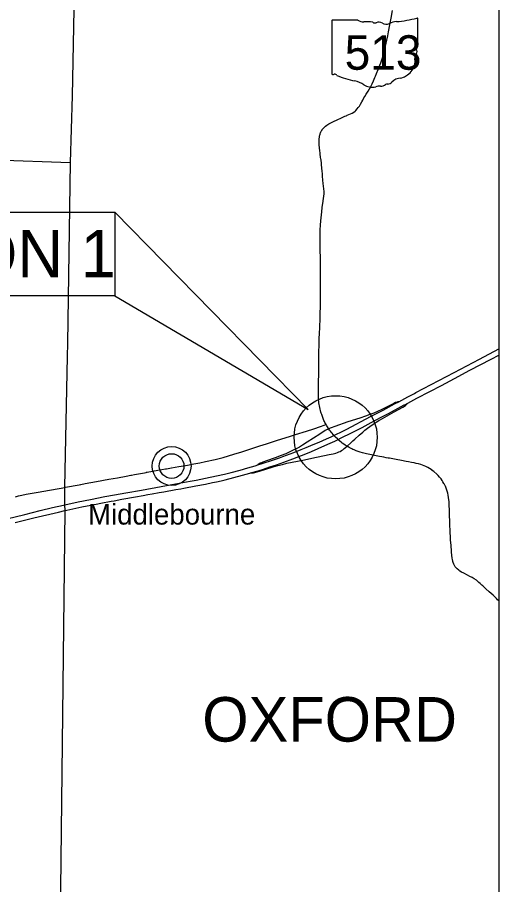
# Model space of a CAD drawing. Extents: x -29.6 to 34, y 0 to 22.
# Drawn here: x -12.475 to -10.748, y 3.392 to 6.503 of the extents above; entities that cross this region are included whole.
import ezdxf

# ---------------------------------------------------------------- set-up
doc = ezdxf.new("R2010")
doc.units = 0
for name, color, linetype in [('BR_P_Gen_Text', 7, 'Continuous'), ('Default', 7, 'Continuous'), ('GM_X_County_Road', 7, 'Continuous'), ('GM_X_Interchange_Ramps', 7, 'Continuous'), ('GM_X_Interstate_Route', 7, 'Continuous'), ('GM_X_State_Route', 7, 'Continuous'), ('GM_X_State_Shield', 7, 'Continuous'), ('GM_X_Township', 7, 'Continuous'), ('GM_X_Township_Text', 7, 'Continuous'), ('GM_X_Unincorporated', 7, 'Continuous'), ('GM_X_Unincorporated_Location', 7, 'Continuous'), ('GM_X_Unincorporated_Text', 7, 'Continuous'), ('GM_X_US_Route', 7, 'Continuous'), ('SH_Text', 7, 'Continuous')]:
    doc.layers.add(name, color=color, linetype=linetype)

msp = doc.modelspace()

# ---------------------------------------------------------------- linework, layer by layer
at = {"layer": 'BR_P_Gen_Text'}
for points in [[(-13.5333, 5.8042), (-12.1246, 5.8042), (-12.1246, 5.504), (-13.5333, 5.504)], [(-12.1246, 5.8042), (-12.1246, 5.504), (-11.4311, 5.0966)]]:
    msp.add_lwpolyline(points, close=True, dxfattribs=at)
at = {"layer": 'Default'}
msp.add_circle((-11.3326, 4.9969), 0.149, dxfattribs=at)
at = {"layer": 'GM_X_County_Road'}
for points in [[(-11.8865, 4.8935), (-11.8639, 4.8975), (-11.8418, 4.9017), (-11.8201, 4.9059), (-11.7991, 4.91), (-11.7653, 4.9176), (-11.7359, 4.9251), (-11.7174, 4.9303), (-11.6985, 4.9359), (-11.6694, 4.945), (-11.6403, 4.9544), (-11.6048, 4.9658), (-11.5812, 4.9733), (-11.5444, 4.9851), (-11.495, 5.0005), (-11.4767, 5.0065), (-11.4371, 5.0195), (-11.4109, 5.0277), (-11.3866, 5.0362), (-11.3733, 5.0405), (-11.3672, 5.0424)], [(-11.94, 4.8838), (-11.9337, 4.885), (-11.9216, 4.8872), (-11.8952, 4.892), (-11.8865, 4.8935)], [(-12.2531, 4.8269), (-12.2486, 4.8276), (-12.2473, 4.8279), (-12.2307, 4.8312), (-12.1911, 4.8381), (-12.1459, 4.8465), (-12.1149, 4.852), (-12.084, 4.8578), (-12.0674, 4.8608), (-12.0653, 4.8612)], [(-12.0653, 4.8612), (-12.0548, 4.863), (-12.0181, 4.87), (-12.0124, 4.8712), (-12.0115, 4.8714)], [(-12.0115, 4.8714), (-12.009, 4.8718), (-11.9895, 4.8753), (-11.971, 4.8785), (-11.9566, 4.8809), (-11.9425, 4.8833), (-11.94, 4.8838)], [(-12.3047, 4.8174), (-12.302, 4.8179), (-12.2531, 4.8269)], [(-12.4817, 4.7837), (-12.471, 4.7865), (-12.459, 4.7894), (-12.443, 4.7926), (-12.3995, 4.8006), (-12.38, 4.8041), (-12.3047, 4.8174)]]:
    msp.add_lwpolyline(points, dxfattribs=at)
at = {"layer": 'GM_X_Interchange_Ramps'}
for points in [[(-11.1062, 5.1247), (-11.1095, 5.1242), (-11.1123, 5.1234), (-11.1178, 5.1214), (-11.1236, 5.1186), (-11.1402, 5.1103), (-11.1668, 5.097), (-11.1826, 5.0895), (-11.1954, 5.0839), (-11.2101, 5.0782), (-11.226, 5.0725), (-11.2454, 5.066), (-11.2886, 5.0519), (-11.335, 5.0361), (-11.3493, 5.0311), (-11.358, 5.0278)], [(-11.2917, 4.965), (-11.2899, 4.9666), (-11.2795, 4.9759), (-11.2709, 4.9837), (-11.2636, 4.9904), (-11.2477, 5.0049), (-11.2355, 5.0158), (-11.2279, 5.0222), (-11.2188, 5.0294), (-11.2104, 5.0357), (-11.198, 5.0443), (-11.1877, 5.051), (-11.1773, 5.0574), (-11.1642, 5.0649), (-11.1229, 5.0878), (-11.0922, 5.1046), (-11.0856, 5.1088), (-11.0819, 5.1116), (-11.0776, 5.1156), (-11.0737, 5.1196)], [(-11.358, 5.0278), (-11.3624, 5.0255), (-11.366, 5.0235), (-11.3699, 5.0211), (-11.3899, 5.008), (-11.4344, 4.9792), (-11.4511, 4.9687), (-11.4621, 4.9621), (-11.4739, 4.9556), (-11.4869, 4.9491), (-11.4996, 4.9432), (-11.5119, 4.9379), (-11.5282, 4.9315), (-11.5495, 4.9237), (-11.5806, 4.9127), (-11.5935, 4.9077), (-11.599, 4.9055), (-11.6029, 4.9037), (-11.6074, 4.9012), (-11.6118, 4.898)], [(-11.6377, 4.8692), (-11.6331, 4.8693), (-11.6274, 4.8701), (-11.622, 4.8711), (-11.6064, 4.8757), (-11.5569, 4.8911), (-11.5401, 4.8959), (-11.5237, 4.9), (-11.5073, 4.9037), (-11.469, 4.9116), (-11.4445, 4.9166), (-11.4177, 4.9221), (-11.3557, 4.935), (-11.3415, 4.9381), (-11.3324, 4.9404), (-11.3258, 4.9425), (-11.3209, 4.9445), (-11.3168, 4.9465), (-11.3117, 4.9494), (-11.3069, 4.9526), (-11.3018, 4.9565), (-11.2917, 4.965)]]:
    msp.add_lwpolyline(points, dxfattribs=at)
at = {"layer": 'GM_X_Interstate_Route'}
for points in [[(-11.0737, 5.1196), (-11.041, 5.1369), (-10.9946, 5.1613), (-10.9529, 5.1833), (-10.9066, 5.2077), (-10.851, 5.2372), (-10.7749, 5.2775), (-10.7478, 5.2918)], [(-11.0498, 5.1544), (-11.0448, 5.1571), (-10.9902, 5.1858), (-10.9075, 5.2298), (-10.8168, 5.2775), (-10.7478, 5.3139)], [(-11.6118, 4.898), (-11.5923, 4.904), (-11.5629, 4.9136), (-11.5342, 4.9234), (-11.5216, 4.9279), (-11.509, 4.9326), (-11.4823, 4.9427), (-11.4563, 4.953), (-11.4385, 4.9602), (-11.4132, 4.9708), (-11.3918, 4.98), (-11.3658, 4.9917), (-11.3493, 4.9992), (-11.3391, 5.0039), (-11.3319, 5.0072), (-11.3119, 5.0168), (-11.2927, 5.0265), (-11.2075, 5.0712), (-11.1627, 5.0948), (-11.121, 5.1168), (-11.1062, 5.1247), (-11.0732, 5.1422), (-11.0498, 5.1544)], [(-11.3266, 4.9878), (-11.3241, 4.989), (-11.3123, 4.9947), (-11.2753, 5.0132), (-11.2379, 5.0322), (-11.2049, 5.0496), (-11.1665, 5.0703), (-11.1434, 5.0827), (-11.0864, 5.1129)], [(-11.0864, 5.1129), (-11.0847, 5.1138), (-11.0737, 5.1196)], [(-11.6377, 4.8692), (-11.611, 4.8771), (-11.5916, 4.8832), (-11.5683, 4.8908), (-11.5451, 4.8986), (-11.5188, 4.9079), (-11.4865, 4.9196), (-11.4653, 4.9277), (-11.4452, 4.9356), (-11.4189, 4.9465), (-11.3948, 4.9569), (-11.3602, 4.9722), (-11.3359, 4.9834), (-11.3266, 4.9878)], [(-12.5124, 4.705), (-12.4478, 4.7204), (-12.3924, 4.7341), (-12.3482, 4.7446), (-12.3096, 4.7535), (-12.3047, 4.7545), (-12.2561, 4.7651), (-12.2127, 4.774), (-12.1607, 4.7841), (-12.1258, 4.7905), (-12.0856, 4.7977), (-12.0288, 4.8078), (-11.9073, 4.8295), (-11.8545, 4.8391), (-11.8334, 4.8431), (-11.7997, 4.85), (-11.7598, 4.8584), (-11.7314, 4.8649), (-11.7076, 4.8708), (-11.6755, 4.8793), (-11.6474, 4.8872), (-11.6218, 4.8949), (-11.6118, 4.898)], [(-12.4828, 4.6916), (-12.416, 4.7078), (-12.3265, 4.729), (-12.3044, 4.7341), (-12.2969, 4.7358), (-12.2867, 4.738), (-12.2644, 4.7428), (-12.2433, 4.7472), (-12.2108, 4.7539), (-12.2074, 4.7545), (-12.192, 4.7576), (-12.1754, 4.7607), (-12.1381, 4.7676), (-12.1272, 4.7696), (-12.0997, 4.7746), (-12.051, 4.7834), (-12.0229, 4.7884), (-12.0068, 4.7913), (-11.9913, 4.794), (-11.9655, 4.7986), (-11.9495, 4.8014), (-11.9059, 4.8092), (-11.8881, 4.8124), (-11.8772, 4.8143), (-11.8343, 4.8223), (-11.7994, 4.8291), (-11.7749, 4.8343), (-11.7607, 4.8375), (-11.7437, 4.8414), (-11.7295, 4.8448), (-11.6985, 4.8526), (-11.6669, 4.8609), (-11.64, 4.8685), (-11.6377, 4.8692)]]:
    msp.add_lwpolyline(points, dxfattribs=at)
at = {"layer": 'GM_X_State_Route'}
for points in [[(-11.3939, 5.1893), (-11.3938, 5.1912), (-11.3937, 5.1987), (-11.3936, 5.2031), (-11.3932, 5.2159), (-11.3931, 5.2235), (-11.3931, 5.2316), (-11.3929, 5.2492), (-11.3928, 5.2634), (-11.3929, 5.269), (-11.3928, 5.2738), (-11.3928, 5.2781), (-11.3928, 5.2811), (-11.3928, 5.2872), (-11.3928, 5.2905), (-11.3928, 5.2946), (-11.3929, 5.3023), (-11.3929, 5.3052), (-11.3923, 5.3261), (-11.3919, 5.3418), (-11.3915, 5.352), (-11.3907, 5.3678), (-11.3898, 5.3918), (-11.3886, 5.4233), (-11.3878, 5.4477), (-11.3874, 5.4585), (-11.3872, 5.465), (-11.3869, 5.4723), (-11.3867, 5.4832), (-11.3867, 5.4865), (-11.3868, 5.4983), (-11.387, 5.5088), (-11.3872, 5.5303), (-11.3873, 5.5461), (-11.3875, 5.5589), (-11.3875, 5.5775), (-11.3875, 5.5932), (-11.3875, 5.6031), (-11.3875, 5.6247), (-11.3875, 5.6433), (-11.3877, 5.6653), (-11.3877, 5.6771), (-11.3879, 5.6864), (-11.3883, 5.7027), (-11.3885, 5.7178), (-11.3884, 5.7271), (-11.3879, 5.7416), (-11.3869, 5.7584), (-11.3856, 5.7729), (-11.3824, 5.8059), (-11.3806, 5.8216), (-11.3784, 5.8371), (-11.3776, 5.8422), (-11.3772, 5.8451), (-11.3761, 5.8532), (-11.375, 5.8624), (-11.3744, 5.8705), (-11.3744, 5.8781), (-11.3751, 5.8877), (-11.3771, 5.9077), (-11.3783, 5.9193), (-11.3795, 5.9334), (-11.3802, 5.9415), (-11.381, 5.9514), (-11.3822, 5.9625), (-11.3834, 5.9749), (-11.3838, 5.9789), (-11.3852, 5.9917), (-11.3856, 5.9951), (-11.3865, 6.002), (-11.3878, 6.0129), (-11.3884, 6.017), (-11.3892, 6.0239), (-11.3899, 6.0285), (-11.3901, 6.0307), (-11.3905, 6.0342), (-11.3909, 6.038), (-11.3915, 6.0431), (-11.3918, 6.0473), (-11.3921, 6.0528), (-11.3921, 6.0567), (-11.3921, 6.0606), (-11.3918, 6.0667), (-11.391, 6.0741), (-11.3904, 6.0781), (-11.3895, 6.0811), (-11.3886, 6.0842), (-11.3878, 6.0866), (-11.3868, 6.0894), (-11.3856, 6.0922), (-11.3844, 6.0946), (-11.3828, 6.0976), (-11.382, 6.0988), (-11.3814, 6.0998), (-11.3807, 6.1007), (-11.3798, 6.102), (-11.3792, 6.1029), (-11.3784, 6.1038), (-11.3776, 6.1048), (-11.3762, 6.1062), (-11.3743, 6.1081), (-11.369, 6.1125), (-11.3639, 6.1163), (-11.3566, 6.1209), (-11.3505, 6.1243), (-11.3407, 6.1292), (-11.3276, 6.1355), (-11.3112, 6.1431), (-11.2995, 6.1482), (-11.2953, 6.1502), (-11.2931, 6.151), (-11.291, 6.152), (-11.2851, 6.1545), (-11.2797, 6.1568), (-11.2728, 6.1601), (-11.2673, 6.1635), (-11.2631, 6.1668), (-11.2601, 6.1696), (-11.2553, 6.1748), (-11.2517, 6.1794), (-11.2476, 6.1852), (-11.2436, 6.1917), (-11.2387, 6.2003), (-11.2354, 6.2064), (-11.2311, 6.214), (-11.2283, 6.2191), (-11.2236, 6.2271), (-11.2163, 6.2389), (-11.2112, 6.2474), (-11.207, 6.255), (-11.202, 6.2649), (-11.1971, 6.2755), (-11.1921, 6.2873), (-11.19, 6.2927), (-11.1864, 6.3013), (-11.1802, 6.3163), (-11.178, 6.3216), (-11.1737, 6.3319), (-11.1702, 6.3405), (-11.1666, 6.351), (-11.1624, 6.365), (-11.1586, 6.3791), (-11.1567, 6.3864), (-11.1546, 6.3949), (-11.1523, 6.4045), (-11.151, 6.4102), (-11.1487, 6.421), (-11.1456, 6.4365), (-11.1428, 6.4513), (-11.1379, 6.4765), (-11.1357, 6.4885), (-11.1337, 6.4999), (-11.1284, 6.528)], [(-11.3672, 5.0424), (-11.3693, 5.0462), (-11.3711, 5.0499), (-11.3731, 5.054), (-11.3745, 5.0572), (-11.3761, 5.0609), (-11.3774, 5.0641), (-11.3788, 5.0679), (-11.3826, 5.0782), (-11.3843, 5.0832), (-11.3856, 5.0876), (-11.3872, 5.0932), (-11.3884, 5.0982), (-11.3898, 5.1039), (-11.3909, 5.1096), (-11.392, 5.1152), (-11.3927, 5.1204), (-11.3934, 5.1262), (-11.3938, 5.1319), (-11.3942, 5.1365), (-11.3943, 5.1386), (-11.3944, 5.1427), (-11.3945, 5.1487), (-11.3944, 5.1544), (-11.3943, 5.1603), (-11.3942, 5.1667), (-11.3941, 5.1712), (-11.3942, 5.1776), (-11.3941, 5.1856), (-11.3939, 5.1893)], [(-11.312, 4.9788), (-11.318, 4.9836), (-11.3232, 4.9882), (-11.3241, 4.989), (-11.3263, 4.9909), (-11.3326, 4.9969), (-11.3346, 4.999), (-11.3391, 5.0039), (-11.3397, 5.0045), (-11.3413, 5.0062), (-11.342, 5.0071), (-11.3452, 5.0112), (-11.3485, 5.0152), (-11.3509, 5.0184), (-11.3523, 5.0202), (-11.3545, 5.0229), (-11.3571, 5.0267), (-11.358, 5.0278), (-11.3598, 5.0304), (-11.3624, 5.0343), (-11.3648, 5.0382), (-11.3672, 5.0424)], [(-11.2917, 4.965), (-11.2956, 4.9672), (-11.298, 4.9688), (-11.3033, 4.9724), (-11.3089, 4.9764), (-11.312, 4.9788)], [(-10.9258, 4.7642), (-10.926, 4.7668), (-10.9265, 4.7731), (-10.9273, 4.7813), (-10.9286, 4.7892), (-10.9303, 4.7963), (-10.9313, 4.8002), (-10.9336, 4.8075), (-10.9362, 4.8147), (-10.939, 4.8216), (-10.9397, 4.8231), (-10.9406, 4.8248), (-10.9435, 4.8301), (-10.9445, 4.8317), (-10.9479, 4.8375), (-10.9508, 4.8423), (-10.9544, 4.8474), (-10.9584, 4.8522), (-10.9603, 4.8545), (-10.9646, 4.8596), (-10.9699, 4.8649), (-10.9804, 4.8742), (-10.986, 4.8784), (-10.9867, 4.8789), (-10.9957, 4.8847), (-11.0022, 4.8886), (-11.0062, 4.8907), (-11.0097, 4.8924), (-11.0154, 4.8951), (-11.0213, 4.8972), (-11.0275, 4.8992), (-11.0351, 4.9013), (-11.0438, 4.9033), (-11.0512, 4.905), (-11.0603, 4.9067), (-11.0707, 4.9087), (-11.0797, 4.9104), (-11.0967, 4.9138), (-11.1152, 4.9171), (-11.14, 4.9217), (-11.144, 4.9224), (-11.152, 4.9238), (-11.1594, 4.9253), (-11.1669, 4.9266), (-11.1757, 4.9284), (-11.1931, 4.9321), (-11.2098, 4.9352), (-11.2221, 4.9378), (-11.236, 4.9411), (-11.2447, 4.9436), (-11.2552, 4.9472), (-11.2595, 4.9489), (-11.2665, 4.9516), (-11.2708, 4.9538), (-11.2748, 4.9557), (-11.2793, 4.958), (-11.2843, 4.9607), (-11.2875, 4.9624), (-11.2917, 4.965)], [(-10.7478, 4.4101), (-10.7517, 4.4143), (-10.7555, 4.4183), (-10.7621, 4.4249), (-10.768, 4.4305), (-10.7818, 4.4431), (-10.7934, 4.4536), (-10.7964, 4.4564), (-10.805, 4.4643), (-10.8081, 4.467), (-10.8137, 4.4721), (-10.8185, 4.4763), (-10.8202, 4.4778), (-10.8226, 4.4798), (-10.8271, 4.484), (-10.8357, 4.4894), (-10.8426, 4.4937), (-10.8511, 4.4982), (-10.8596, 4.5025), (-10.8731, 4.5092), (-10.8815, 4.5133), (-10.8873, 4.517), (-10.8912, 4.52), (-10.8964, 4.5246), (-10.9006, 4.5293), (-10.9035, 4.5329), (-10.9064, 4.5377), (-10.9086, 4.5424), (-10.9107, 4.5474), (-10.9122, 4.552), (-10.9126, 4.5533), (-10.9133, 4.5557), (-10.9138, 4.5582), (-10.9147, 4.5634), (-10.9152, 4.566), (-10.9158, 4.5716), (-10.9172, 4.5878), (-10.9176, 4.5963), (-10.918, 4.6015), (-10.9184, 4.6055), (-10.9186, 4.6084), (-10.9201, 4.6293), (-10.9206, 4.6368), (-10.921, 4.6421), (-10.9216, 4.6531), (-10.9222, 4.6621), (-10.9229, 4.6819), (-10.9234, 4.6975), (-10.924, 4.7155), (-10.9242, 4.7198), (-10.9245, 4.7261), (-10.9246, 4.7334), (-10.9248, 4.7405), (-10.9251, 4.7485), (-10.9254, 4.7558), (-10.9255, 4.7587), (-10.9258, 4.7642)]]:
    msp.add_lwpolyline(points, dxfattribs=at)
at = {"layer": 'GM_X_State_Shield'}
for p, q in [((-11.3468, 6.4897), (-11.3468, 6.3021)), ((-11.2533, 6.4929), (-11.3438, 6.4929)), ((-11.0378, 6.3994), (-11.0378, 6.4975)), ((-11.0378, 6.3994), (-11.0378, 6.3994))]:
    msp.add_line(p, q, dxfattribs=at)
for centre, major_axis, start_param, end_param in [((-11.3433, 6.4901), (0.00358, 0), 1.712693, 3.28349), ((-11.2317, 6.5147), (0.0347, 0), 4.042523, 4.731795), ((-11.2202, 6.3876), (0.1246, 0), 1.404758, 1.657858), ((-11.1919, 6.491), (0.01, 0), 3.836095, 5.185415), ((-11.1772, 6.4694), (0.0208, 0), 0.950623, 2.079405), ((-11.1503, 6.4991), (0.0251, 0), 4.081561, 5.145723), ((-11.1061, 6.4356), (0.0659, 0), 1.699011, 2.107814), ((-11.1479, 6.7487), (0.3277, 0), 4.814394, 5.042369), ((-11.0412, 6.498), (0.00344, 0), 6.141152, 7.989035), ((-11.0386, 6.3922), (0.00532, 0), 1.883978, 3.671073), ((-11.0725, 6.3798), (0.032, 0), 5.934695, 6.695948), ((-11.0415, 6.399), (0.00368, 0), 5.05454, 6.418171), ((-11.1295, 6.3458), (0.082, 0), 5.101752, 6.440018), ((-11.0255, 6.3583), (0.0232, 0), 2.387724, 3.262537), ((-11.3432, 6.3016), (0.00361, 0), 3.00124, 4.508301), ((-11.3427, 6.3208), (0.0276, 0), 4.665946, 4.897461), ((-11.337, 6.2912), (0.00994, 0), 0.519207, 1.627899), ((-11.2116, 6.4598), (0.2366, 0), 4.195997, 4.488961), ((-11.095, 6.2494), (0.0449, 0), 1.647645, 2.488434), ((-11.2821, 6.2178), (0.074, 0), 0.823519, 1.323587), ((-11.2021, 6.2903), (0.047, 0), 4.026481, 4.996735), ((-11.1749, 6.2254), (0.0386, 0), 1.495662, 1.94098), ((-11.1715, 6.2762), (0.025, 0), 4.691044, 5.507374), ((-11.1488, 6.2581), (0.00705, 0), 1.147584, 2.315152), ((-11.1518, 6.2839), (0.0265, 0), 4.937069, 5.64225)]:
    msp.add_ellipse(centre, major_axis=major_axis, ratio=0.8, start_param=start_param, end_param=end_param, dxfattribs=at)
at = {"layer": 'GM_X_Township'}
for points in [[(-10.7478, 7.0493), (-10.7917, 7.05), (-10.9427, 7.0551), (-11.0852, 7.0579), (-12.1902, 7.0754), (-12.2612, 7.0767), (-12.2665, 6.8423), (-12.2783, 6.2218), (-12.2845, 5.982), (-12.2945, 5.335), (-12.2964, 5.2867), (-12.3049, 4.8179), (-12.3049, 4.755), (-12.3046, 4.7346), (-12.3198, 3.3777), (-12.3286, 2.3826), (-12.1886, 2.3813), (-11.4346, 2.3766), (-11.1566, 2.3751), (-10.8647, 2.3724), (-10.7478, 2.3716)], [(-16.907, 6.0998), (-16.7922, 6.098), (-15.3983, 6.0749), (-14.5953, 6.0489), (-14.3095, 6.0432), (-13.3257, 6.0175), (-12.5552, 5.9919), (-12.2845, 5.982)]]:
    msp.add_lwpolyline(points, dxfattribs=at)
at = {"layer": 'GM_X_Unincorporated'}
for radius in [0.0698, 0.0442]:
    msp.add_circle((-11.9212, 4.8939), radius, dxfattribs=at)
at = {"layer": 'GM_X_Unincorporated_Location'}
msp.add_line((-11.9212, 4.8939), (-11.9212, 4.8939), dxfattribs=at)
at = {"layer": 'GM_X_US_Route'}
for points in [[(-11.0737, 5.1196), (-11.041, 5.1369), (-10.9946, 5.1613), (-10.9529, 5.1833), (-10.9066, 5.2077), (-10.851, 5.2372), (-10.7749, 5.2775), (-10.7478, 5.2918)], [(-11.3266, 4.9878), (-11.3241, 4.989), (-11.3123, 4.9947), (-11.2753, 5.0132), (-11.2379, 5.0322), (-11.2049, 5.0496), (-11.1665, 5.0703), (-11.1434, 5.0827), (-11.0864, 5.1129)], [(-11.0864, 5.1129), (-11.0847, 5.1138), (-11.0737, 5.1196)], [(-11.6377, 4.8692), (-11.611, 4.8771), (-11.5916, 4.8832), (-11.5683, 4.8908), (-11.5451, 4.8986), (-11.5188, 4.9079), (-11.4865, 4.9196), (-11.4653, 4.9277), (-11.4452, 4.9356), (-11.4189, 4.9465), (-11.3948, 4.9569), (-11.3602, 4.9722), (-11.3359, 4.9834), (-11.3266, 4.9878)], [(-12.4828, 4.6916), (-12.416, 4.7078), (-12.3265, 4.729), (-12.3044, 4.7341), (-12.2969, 4.7358), (-12.2867, 4.738), (-12.2644, 4.7428), (-12.2433, 4.7472), (-12.2108, 4.7539), (-12.2074, 4.7545), (-12.192, 4.7576), (-12.1754, 4.7607), (-12.1381, 4.7676), (-12.1272, 4.7696), (-12.0997, 4.7746), (-12.051, 4.7834), (-12.0229, 4.7884), (-12.0068, 4.7913), (-11.9913, 4.794), (-11.9655, 4.7986), (-11.9495, 4.8014), (-11.9059, 4.8092), (-11.8881, 4.8124), (-11.8772, 4.8143), (-11.8343, 4.8223), (-11.7994, 4.8291), (-11.7749, 4.8343), (-11.7607, 4.8375), (-11.7437, 4.8414), (-11.7295, 4.8448), (-11.6985, 4.8526), (-11.6669, 4.8609), (-11.64, 4.8685), (-11.6377, 4.8692)]]:
    msp.add_lwpolyline(points, dxfattribs=at)
at = {"layer": 'SH_Text'}
msp.add_lwpolyline([(-29.5833, 13.2079), (-10.7478, 13.2079), (-10.7478, 1.0528), (-29.5833, 1.0528)], close=True, dxfattribs=at)

# ---------------------------------------------------------------- texts
at = {"layer": 'BR_P_Gen_Text'}
msp.add_text('LOCATION 1', height=0.17, dxfattribs=at).set_placement((-13.4726, 5.5708))
at = {"layer": 'GM_X_State_Shield'}
msp.add_text('513', height=0.1236, dxfattribs=at).set_placement((-11.3004, 6.3153))
at = {"layer": 'GM_X_Township_Text'}
msp.add_text('OXFORD', height=0.1598, rotation=0, dxfattribs=at).set_placement((-11.8113, 3.9054))
at = {"layer": 'GM_X_Unincorporated_Text'}
msp.add_text('Middlebourne', height=0.074041, rotation=0, dxfattribs=at).set_placement((-12.221, 4.6839))

doc.saveas('drawing.dxf')
